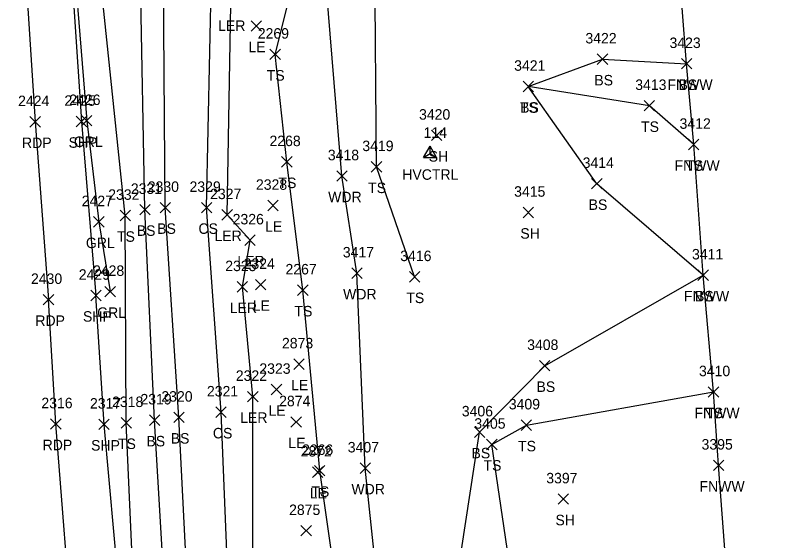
# Model space of a CAD drawing. Extents: x 1650221 to 1650634, y 244606 to 249996.
# Drawn here: x 1650339.8 to 1650486.8, y 246621.5 to 246721.6 of the extents above; entities that cross this region are included whole.
import ezdxf

# ---------------------------------------------------------------- set-up
doc = ezdxf.new("R2010")
doc.units = 0
for name, color, linetype in [('C_A', 7, 'Continuous'), ('C_I', 7, 'Continuous'), ('CPSM', 7, 'Continuous'), ('L_A', 7, 'Continuous'), ('L_I', 7, 'Continuous'), ('L_TIC', 7, 'Continuous'), ('LARO', 7, 'Continuous'), ('LAWA', 7, 'Continuous'), ('LELB', 7, 'Continuous'), ('LFNC', 7, 'Continuous'), ('LSOGP', 7, 'Continuous'), ('P_A', 7, 'Continuous'), ('P_I', 7, 'Continuous'), ('P_TIC', 7, 'Continuous'), ('PET', 7, 'Continuous'), ('PSP', 7, 'Continuous'), ('R_A', 7, 'Continuous'), ('R_I', 7, 'Continuous'), ('R_TIC', 7, 'Continuous'), ('RGR', 7, 'Continuous')]:
    doc.layers.add(name, color=color, linetype=linetype)

msp = doc.modelspace()

# ---------------------------------------------------------------- linework, layer by layer
at = {"layer": 'CPSM'}
for p, q in [((1650417.57, 246694.55), (1650418.82, 246696.71)), ((1650420.07, 246694.55), (1650418.82, 246696.71)), ((1650418.82, 246695.27), (1650418.82, 246696.71)), ((1650417.57, 246694.55), (1650418.82, 246695.27)), ((1650418.82, 246695.27), (1650418.82, 246695.27)), ((1650418.82, 246695.27), (1650420.07, 246694.55)), ((1650417.57, 246694.55), (1650420.07, 246694.55))]:
    msp.add_line(p, q, dxfattribs=at)
at = {"layer": 'L_TIC'}
for points in [[(1650384.7, 246718.6), (1650386.7, 246720.6)], [(1650386.7, 246718.6), (1650384.7, 246720.6)], [(1650388.29, 246713.19), (1650390.29, 246715.19)], [(1650390.29, 246713.19), (1650388.29, 246715.19)], [(1650450.69, 246712.27), (1650452.69, 246714.27)], [(1650452.69, 246712.27), (1650450.69, 246714.27)], [(1650466.72, 246711.4), (1650468.72, 246713.4)], [(1650468.72, 246711.4), (1650466.72, 246713.4)], [(1650466.72, 246711.4), (1650468.72, 246713.4)], [(1650468.72, 246711.4), (1650466.72, 246713.4)], [(1650436.54, 246707.06), (1650438.54, 246709.06)], [(1650438.54, 246707.06), (1650436.54, 246709.06)], [(1650436.54, 246707.06), (1650438.54, 246709.06)], [(1650438.54, 246707.06), (1650436.54, 246709.06)], [(1650459.62, 246703.4), (1650461.62, 246705.4)], [(1650461.62, 246703.4), (1650459.62, 246705.4)], [(1650419.07, 246697.74), (1650421.07, 246699.74)], [(1650421.07, 246697.74), (1650419.07, 246699.74)], [(1650468.07, 246695.99), (1650470.07, 246697.99)], [(1650470.07, 246695.99), (1650468.07, 246697.99)], [(1650468.07, 246695.99), (1650470.07, 246697.99)], [(1650470.07, 246695.99), (1650468.07, 246697.99)], [(1650390.51, 246692.69), (1650392.51, 246694.69)], [(1650392.51, 246692.69), (1650390.51, 246694.69)], [(1650407.61, 246691.74), (1650409.61, 246693.74)], [(1650409.61, 246691.74), (1650407.61, 246693.74)], [(1650401.03, 246690), (1650403.03, 246692)], [(1650403.03, 246690), (1650401.03, 246692)], [(1650449.6, 246688.53), (1650451.6, 246690.53)], [(1650451.6, 246688.53), (1650449.6, 246690.53)], [(1650387.89, 246684.36), (1650389.89, 246686.36)], [(1650389.89, 246684.36), (1650387.89, 246686.36)], [(1650363.47, 246683.58), (1650365.47, 246685.58)], [(1650365.47, 246683.58), (1650363.47, 246685.58)], [(1650367.35, 246683.96), (1650369.35, 246685.96)], [(1650369.35, 246683.96), (1650367.35, 246685.96)], [(1650375.23, 246683.96), (1650377.23, 246685.96)], [(1650377.23, 246683.96), (1650375.23, 246685.96)], [(1650436.54, 246683.04), (1650438.54, 246685.04)], [(1650438.54, 246683.04), (1650436.54, 246685.04)], [(1650359.73, 246682.45), (1650361.73, 246684.45)], [(1650361.73, 246682.45), (1650359.73, 246684.45)], [(1650379.15, 246682.58), (1650381.15, 246684.58)], [(1650381.15, 246682.58), (1650379.15, 246684.58)], [(1650383.51, 246677.76), (1650385.51, 246679.76)], [(1650385.51, 246677.76), (1650383.51, 246679.76)], [(1650403.88, 246671.46), (1650405.88, 246673.46)], [(1650405.88, 246671.46), (1650403.88, 246673.46)], [(1650414.88, 246670.76), (1650416.88, 246672.76)], [(1650416.88, 246670.76), (1650414.88, 246672.76)], [(1650469.88, 246671.08), (1650471.88, 246673.08)], [(1650471.88, 246671.08), (1650469.88, 246673.08)], [(1650469.88, 246671.08), (1650471.88, 246673.08)], [(1650471.88, 246671.08), (1650469.88, 246673.08)], [(1650382.04, 246668.85), (1650384.04, 246670.85)], [(1650384.04, 246668.85), (1650382.04, 246670.85)], [(1650385.54, 246669.28), (1650387.54, 246671.28)], [(1650387.54, 246669.28), (1650385.54, 246671.28)], [(1650393.57, 246668.22), (1650395.57, 246670.22)], [(1650395.57, 246668.22), (1650393.57, 246670.22)], [(1650392.85, 246654.12), (1650394.85, 246656.12)], [(1650394.85, 246654.12), (1650392.85, 246656.12)], [(1650439.67, 246653.81), (1650441.67, 246655.81)], [(1650441.67, 246653.81), (1650439.67, 246655.81)], [(1650388.54, 246649.27), (1650390.54, 246651.27)], [(1650390.54, 246649.27), (1650388.54, 246651.27)], [(1650384.05, 246647.92), (1650386.05, 246649.92)], [(1650386.05, 246647.92), (1650384.05, 246649.92)], [(1650471.86, 246648.81), (1650473.86, 246650.81)], [(1650473.86, 246648.81), (1650471.86, 246650.81)], [(1650471.86, 246648.81), (1650473.86, 246650.81)], [(1650473.86, 246648.81), (1650471.86, 246650.81)], [(1650377.98, 246644.95), (1650379.98, 246646.95)], [(1650379.98, 246644.95), (1650377.98, 246646.95)], [(1650365.31, 246643.43), (1650367.31, 246645.43)], [(1650367.31, 246643.43), (1650365.31, 246645.43)], [(1650369.95, 246643.96), (1650371.95, 246645.96)], [(1650371.95, 246643.96), (1650369.95, 246645.96)], [(1650359.91, 246642.93), (1650361.91, 246644.93)], [(1650361.91, 246642.93), (1650359.91, 246644.93)], [(1650392.31, 246643.09), (1650394.31, 246645.09)], [(1650394.31, 246643.09), (1650392.31, 246645.09)], [(1650436.18, 246642.48), (1650438.18, 246644.48)], [(1650438.18, 246642.48), (1650436.18, 246644.48)], [(1650427.27, 246641.15), (1650429.27, 246643.15)], [(1650429.27, 246641.15), (1650427.27, 246643.15)], [(1650429.6, 246638.8), (1650431.6, 246640.8)], [(1650431.6, 246638.8), (1650429.6, 246640.8)], [(1650472.83, 246634.82), (1650474.83, 246636.82)], [(1650474.83, 246634.82), (1650472.83, 246636.82)], [(1650396.41, 246633.5), (1650398.41, 246635.5)], [(1650398.41, 246633.5), (1650396.41, 246635.5)], [(1650396.78, 246633.8), (1650398.78, 246635.8)], [(1650398.78, 246633.8), (1650396.78, 246635.8)], [(1650405.47, 246634.27), (1650407.47, 246636.27)], [(1650407.47, 246634.27), (1650405.47, 246636.27)], [(1650443.23, 246628.38), (1650445.23, 246630.38)], [(1650445.23, 246628.38), (1650443.23, 246630.38)], [(1650394.21, 246622.34), (1650396.21, 246624.34)], [(1650396.21, 246622.34), (1650394.21, 246624.34)]]:
    msp.add_lwpolyline(points, dxfattribs=at)
at = {"layer": 'LARO'}
msp.add_lwpolyline([(1650385.03, 246598.74), (1650385.05, 246648.92), (1650383.04, 246669.85), (1650384.51, 246678.76), (1650380.15, 246683.58), (1650380.84, 246723.67), (1650382.06, 246738.73), (1650384.58, 246748.9), (1650380.15, 246753.92), (1650379.38, 246768.54), (1650378.69, 246789.32), (1650378.2, 246794.91)], dxfattribs=at)
at = {"layer": 'LAWA'}
msp.add_lwpolyline([(1650408.99, 246611.27), (1650406.47, 246635.27), (1650404.88, 246672.46), (1650402.03, 246691), (1650398.7, 246731.36), (1650398.69, 246740.76), (1650399.82, 246757.07), (1650398.26, 246761.36), (1650401.34, 246765.66), (1650397.98, 246772.41), (1650398.12, 246782.32), (1650386.61, 246784.94)], dxfattribs=at)
at = {"layer": 'LELB'}
for points in [[(1650393.27, 246215.06), (1650388.59, 246258.03), (1650385.3, 246297.22), (1650382.89, 246338.27), (1650379.78, 246382.54), (1650376.7, 246415.11), (1650373.39, 246460.52), (1650370.35, 246509.11), (1650367.73, 246551.79), (1650362.79, 246601.35), (1650360.91, 246643.93), (1650360.73, 246683.45), (1650355.99, 246728.59), (1650353.01, 246770.02), (1650352.21, 246793.58), (1650347.7, 246827.18)], [(1650402.92, 246599.27), (1650397.78, 246634.8), (1650394.57, 246669.22), (1650391.51, 246693.69), (1650389.29, 246714.19), (1650398.32, 246750.22), (1650391.13, 246755.18), (1650391.46, 246767.34), (1650381.76, 246778.61), (1650387.76, 246790.38), (1650393.6, 246805.06)], [(1650415.88, 246671.76), (1650408.61, 246692.74), (1650408.27, 246732.32), (1650411.06, 246748.25), (1650427.9, 246749.14), (1650447.8, 246762.5), (1650450.82, 246774.89), (1650455.51, 246787.22), (1650459.2, 246795.67)], [(1650406.66, 246218.25), (1650409.74, 246258.01), (1650404.96, 246296.74), (1650400.85, 246340.5), (1650395.59, 246379.71), (1650393.17, 246415.1), (1650394.55, 246457.78), (1650389.36, 246506.84), (1650386.12, 246550.61), (1650380.92, 246598.97), (1650378.98, 246645.95), (1650376.23, 246684.96), (1650377.19, 246729.69), (1650373.96, 246768.95), (1650374.9, 246794.97)], [(1650398.42, 246215.35), (1650393.5, 246258.25), (1650390.33, 246297.07), (1650387.57, 246339.17), (1650383.09, 246382.59), (1650381.54, 246415.75), (1650379.32, 246460.8), (1650374.72, 246508.95), (1650372.6, 246551.63), (1650368.85, 246601.31), (1650366.31, 246644.43), (1650364.47, 246684.58), (1650363.63, 246728.26), (1650358.66, 246769.4), (1650355.43, 246788.13), (1650360.4, 246788.44)], [(1650402.25, 246216.69), (1650398.47, 246258.76), (1650395.79, 246297.15), (1650391.97, 246340.1), (1650387.54, 246382.07), (1650385.71, 246415.98), (1650383.05, 246460.21), (1650379.09, 246508.87), (1650375.79, 246552.14), (1650373.14, 246601), (1650370.95, 246644.96), (1650368.35, 246684.96), (1650368, 246727.84), (1650362.74, 246769.21), (1650360.4, 246788.44)], [(1650479.19, 246312.48), (1650486.78, 246343.04), (1650484.86, 246368.89), (1650480.94, 246392.32), (1650477.18, 246421.11), (1650468.88, 246443.02), (1650461.43, 246474.29), (1650459.99, 246504.26), (1650455.48, 246533.7), (1650468.39, 246557.95), (1650462.64, 246596.83), (1650458.65, 246616.06), (1650445.95, 246610.52), (1650432.73, 246599.27), (1650420.88, 246596.79), (1650423.87, 246613.47), (1650428.27, 246642.15), (1650440.67, 246654.81), (1650470.88, 246672.08), (1650450.6, 246689.53), (1650437.54, 246708.06), (1650451.69, 246713.27), (1650467.72, 246712.4)], [(1650469.07, 246696.99), (1650460.62, 246704.4), (1650437.54, 246708.06)], [(1650432.73, 246599.27), (1650434.11, 246616.07), (1650430.6, 246639.8), (1650437.18, 246643.48), (1650472.86, 246649.81)]]:
    msp.add_lwpolyline(points, dxfattribs=at)
at = {"layer": 'LFNC'}
msp.add_lwpolyline([(1650476.37, 246602.1), (1650473.83, 246635.82), (1650472.86, 246649.81), (1650470.88, 246672.08), (1650469.07, 246696.99), (1650467.72, 246712.4), (1650466.06, 246733.8), (1650464.07, 246765.5), (1650462.64, 246787.71), (1650459.2, 246795.67), (1650459.39, 246802.96), (1650460.29, 246812.05), (1650460.05, 246825.27)], dxfattribs=at)
at = {"layer": 'LSOGP'}
msp.add_lwpolyline([(1650476.37, 246602.1), (1650473.83, 246635.82), (1650472.86, 246649.81), (1650470.88, 246672.08), (1650469.07, 246696.99), (1650467.72, 246712.4), (1650466.06, 246733.8), (1650464.07, 246765.5), (1650462.64, 246787.71), (1650459.2, 246795.67), (1650459.39, 246802.96), (1650460.29, 246812.05), (1650460.05, 246825.27)], dxfattribs=at)
at = {"layer": 'P_TIC'}
for points in [[(1650342.55, 246700.32), (1650344.55, 246702.32)], [(1650344.55, 246700.32), (1650342.55, 246702.32)], [(1650351.38, 246700.38), (1650353.38, 246702.38)], [(1650353.38, 246700.38), (1650351.38, 246702.38)], [(1650354.13, 246667.21), (1650356.13, 246669.21)], [(1650356.13, 246667.21), (1650354.13, 246669.21)], [(1650354.13, 246667.21), (1650356.13, 246669.21)], [(1650356.13, 246667.21), (1650354.13, 246669.21)], [(1650345.09, 246666.41), (1650347.09, 246668.41)], [(1650347.09, 246666.41), (1650345.09, 246668.41)], [(1650345.09, 246666.41), (1650347.09, 246668.41)], [(1650347.09, 246666.41), (1650345.09, 246668.41)], [(1650346.48, 246642.7), (1650348.48, 246644.7)], [(1650348.48, 246642.7), (1650346.48, 246644.7)], [(1650355.68, 246642.63), (1650357.68, 246644.63)], [(1650357.68, 246642.63), (1650355.68, 246644.63)]]:
    msp.add_lwpolyline(points, dxfattribs=at)
at = {"layer": 'PET'}
for points in [[(1650303.59, 247255.04), (1650306.81, 247216.14), (1650310.51, 247167.04), (1650313.87, 247117.51), (1650317.79, 247067.14), (1650321.46, 247013.25), (1650325.74, 246955.86), (1650329.2, 246907.19), (1650332.99, 246853.31), (1650336.64, 246798.8), (1650340.79, 246743.67), (1650343.55, 246701.32), (1650346.09, 246667.41)], [(1650378.63, 246214.91), (1650375.8, 246256.56), (1650373.01, 246296.44), (1650370.08, 246336.2), (1650366.98, 246382.9), (1650364.95, 246414.8), (1650361.94, 246459.78), (1650357.93, 246508.74), (1650354.58, 246551.74), (1650350.86, 246600.91), (1650347.48, 246643.7), (1650346.09, 246667.41)]]:
    msp.add_lwpolyline(points, dxfattribs=at)
at = {"layer": 'PSP'}
for points in [[(1650307.74, 247242.22), (1650310.23, 247216.37), (1650315.19, 247167.56), (1650319.94, 247117.42), (1650324.85, 247068), (1650329.68, 247013.47), (1650333.89, 246957.27), (1650337.47, 246907.25), (1650341.57, 246853.3), (1650345.82, 246798.32), (1650349.51, 246744.26), (1650352.38, 246701.38), (1650355.13, 246668.21)], [(1650388.25, 246215.07), (1650385.02, 246257.59), (1650382.12, 246297.01), (1650379.04, 246337.67), (1650376.28, 246382.91), (1650373.45, 246415.13), (1650370.45, 246460.18), (1650366.83, 246508.93), (1650363.56, 246551.91), (1650360.5, 246601.39), (1650356.68, 246643.63), (1650355.13, 246668.21)]]:
    msp.add_lwpolyline(points, dxfattribs=at)
at = {"layer": 'R_TIC'}
for points in [[(1650352.37, 246700.53), (1650354.37, 246702.53)], [(1650354.37, 246700.53), (1650352.37, 246702.53)], [(1650354.68, 246681.24), (1650356.68, 246683.24)], [(1650356.68, 246681.24), (1650354.68, 246683.24)], [(1650356.83, 246667.94), (1650358.83, 246669.94)], [(1650358.83, 246667.94), (1650356.83, 246669.94)]]:
    msp.add_lwpolyline(points, dxfattribs=at)
at = {"layer": 'RGR'}
msp.add_lwpolyline([(1650308.18, 247241.07), (1650310.55, 247216.53), (1650315.55, 247167.77), (1650320.43, 247117.51), (1650325.42, 247068.18), (1650330.46, 247013.43), (1650334.74, 246957.48), (1650338.49, 246907.23), (1650342.31, 246853.82), (1650346.19, 246798.3), (1650349.87, 246744.52), (1650353.37, 246701.53), (1650355.68, 246682.24), (1650357.83, 246668.94)], dxfattribs=at)

# ---------------------------------------------------------------- texts
at = {"layer": 'C_A'}
msp.add_text('HVCTRL', height=2, dxfattribs=at).set_placement((1650413.52, 246690.27))
at = {"layer": 'C_I'}
msp.add_text('114', height=2, dxfattribs=at).set_placement((1650417.59, 246698.27))
at = {"layer": 'L_A'}
for s, p in [('LER', (1650378.42, 246718.67)), ('LE', (1650384.19, 246714.6)), ('TS', (1650387.7, 246709.19)), ('BS', (1650450.13, 246708.27)), ('FNWW', (1650464.06, 246707.4)), ('BS', (1650466.16, 246707.4)), ('TS', (1650435.95, 246703.06)), ('BS', (1650435.98, 246703.06)), ('TS', (1650459.03, 246699.4)), ('SH', (1650418.56, 246693.74)), ('FNWW', (1650465.42, 246691.99)), ('TS', (1650467.48, 246691.99)), ('TS', (1650389.92, 246688.69)), ('TS', (1650407.02, 246687.74)), ('WDR', (1650399.39, 246686)), ('BS', (1650449.04, 246684.53)), ('BS', (1650366.8, 246679.96)), ('CS', (1650374.67, 246679.96)), ('LE', (1650387.38, 246680.36)), ('BS', (1650362.91, 246679.58)), ('LER', (1650377.73, 246678.58)), ('SH', (1650436.03, 246679.04)), ('TS', (1650359.14, 246678.45)), ('LER', (1650382.09, 246673.76)), ('WDR', (1650402.24, 246667.46)), ('TS', (1650414.29, 246666.76)), ('FNWW', (1650467.22, 246667.08)), ('BS', (1650469.32, 246667.08)), ('LE', (1650385.03, 246665.28)), ('LER', (1650380.63, 246664.85)), ('TS', (1650392.98, 246664.22)), ('LE', (1650392.34, 246650.12)), ('BS', (1650439.11, 246649.81)), ('LE', (1650388.03, 246645.27)), ('FNWW', (1650469.21, 246644.81)), ('TS', (1650471.27, 246644.81)), ('LER', (1650382.63, 246643.92)), ('CS', (1650377.42, 246640.95)), ('TS', (1650359.32, 246638.93)), ('BS', (1650364.75, 246639.43)), ('BS', (1650369.39, 246639.96)), ('LE', (1650391.8, 246639.09)), ('TS', (1650435.59, 246638.48)), ('BS', (1650426.71, 246637.15)), ('TS', (1650429.01, 246634.8)), ('WDR', (1650403.83, 246630.27)), ('FNWW', (1650470.17, 246630.82)), ('LE', (1650395.9, 246629.5)), ('TS', (1650396.19, 246629.8)), ('SH', (1650442.72, 246624.38))]:
    msp.add_text(s, height=2, dxfattribs=at).set_placement(p)
at = {"layer": 'L_I'}
for s, p in [('2269', (1650385.98, 246717.19)), ('3422', (1650448.43, 246716.27)), ('3423', (1650464.46, 246715.4)), ('3423', (1650464.46, 246715.4)), ('3421', (1650434.85, 246711.06)), ('3421', (1650434.85, 246711.06)), ('3413', (1650457.93, 246707.4)), ('3420', (1650416.72, 246701.74)), ('3412', (1650466.38, 246699.99)), ('3412', (1650466.38, 246699.99)), ('2268', (1650388.21, 246696.69)), ('3419', (1650405.91, 246695.74)), ('3418', (1650399.34, 246694)), ('3414', (1650447.91, 246692.53)), ('2331', (1650361.78, 246687.58)), ('2330', (1650365.01, 246687.96)), ('2329', (1650372.97, 246687.96)), ('2328', (1650385.63, 246688.36)), ('2332', (1650357.47, 246686.45)), ('2327', (1650376.89, 246686.58)), ('3415', (1650434.85, 246687.04)), ('2326', (1650381.19, 246681.76)), ('3417', (1650402.19, 246675.46)), ('3416', (1650413.14, 246674.76)), ('3411', (1650468.75, 246675.08)), ('3411', (1650468.75, 246675.08)), ('2325', (1650379.78, 246672.85)), ('2324', (1650383.28, 246673.28)), ('2267', (1650391.26, 246672.22)), ('2873', (1650390.59, 246658.12)), ('3408', (1650437.33, 246657.81)), ('2323', (1650386.28, 246653.27)), ('3410', (1650470.08, 246652.81)), ('3410', (1650470.08, 246652.81)), ('2322', (1650381.79, 246651.92)), ('2320', (1650367.6, 246647.96)), ('2321', (1650376.29, 246648.95)), ('2318', (1650358.21, 246646.93)), ('2319', (1650363.61, 246647.43)), ('2874', (1650390.05, 246647.09)), ('3409', (1650433.83, 246646.48)), ('3406', (1650424.87, 246645.15)), ('3405', (1650427.26, 246642.8)), ('3395', (1650470.57, 246638.82)), ('2872', (1650394.15, 246637.5)), ('2266', (1650394.42, 246637.8)), ('3407', (1650403.13, 246638.27)), ('3397', (1650440.97, 246632.38)), ('2875', (1650391.95, 246626.34))]:
    msp.add_text(s, height=2, dxfattribs=at).set_placement(p)
at = {"layer": 'P_A'}
for s, p in [('RDP', (1650341.04, 246696.32)), ('SHP', (1650349.92, 246696.38)), ('RDP', (1650343.58, 246662.41)), ('RDP', (1650343.58, 246662.41)), ('SHP', (1650352.66, 246663.21)), ('SHP', (1650352.66, 246663.21)), ('RDP', (1650344.97, 246638.7)), ('SHP', (1650354.21, 246638.63))]:
    msp.add_text(s, height=2, dxfattribs=at).set_placement(p)
at = {"layer": 'P_I'}
for s, p in [('2424', (1650340.29, 246704.32)), ('2425', (1650349.12, 246704.38)), ('2429', (1650351.86, 246671.21)), ('2429', (1650351.86, 246671.21)), ('2430', (1650342.75, 246670.41)), ('2430', (1650342.75, 246670.41)), ('2316', (1650344.73, 246646.7)), ('2317', (1650353.99, 246646.63))]:
    msp.add_text(s, height=2, dxfattribs=at).set_placement(p)
at = {"layer": 'R_A'}
for p in [(1650350.91, 246696.53), (1650353.22, 246677.24), (1650355.37, 246663.94)]:
    msp.add_text('GRL', height=2, dxfattribs=at).set_placement(p)
at = {"layer": 'R_I'}
for s, p in [('2426', (1650350.05, 246704.53)), ('2427', (1650352.42, 246685.24)), ('2428', (1650354.57, 246671.94))]:
    msp.add_text(s, height=2, dxfattribs=at).set_placement(p)

doc.saveas('drawing.dxf')
